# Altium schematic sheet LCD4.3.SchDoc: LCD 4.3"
size A4; Date: Not used; ApprovedBy: Not used; CheckedBy: Not used; Author: Not used; CompanyName: STMicroelectronics; DrawnBy: Not used; Engineer: Not used; Organization: Not used; Address1: Not used; Address2: Not used; Address3: Not used; Address4: Not used; DocumentNumber: 10; Revision: Not used; SheetNumber: 10; SheetTotal: 17
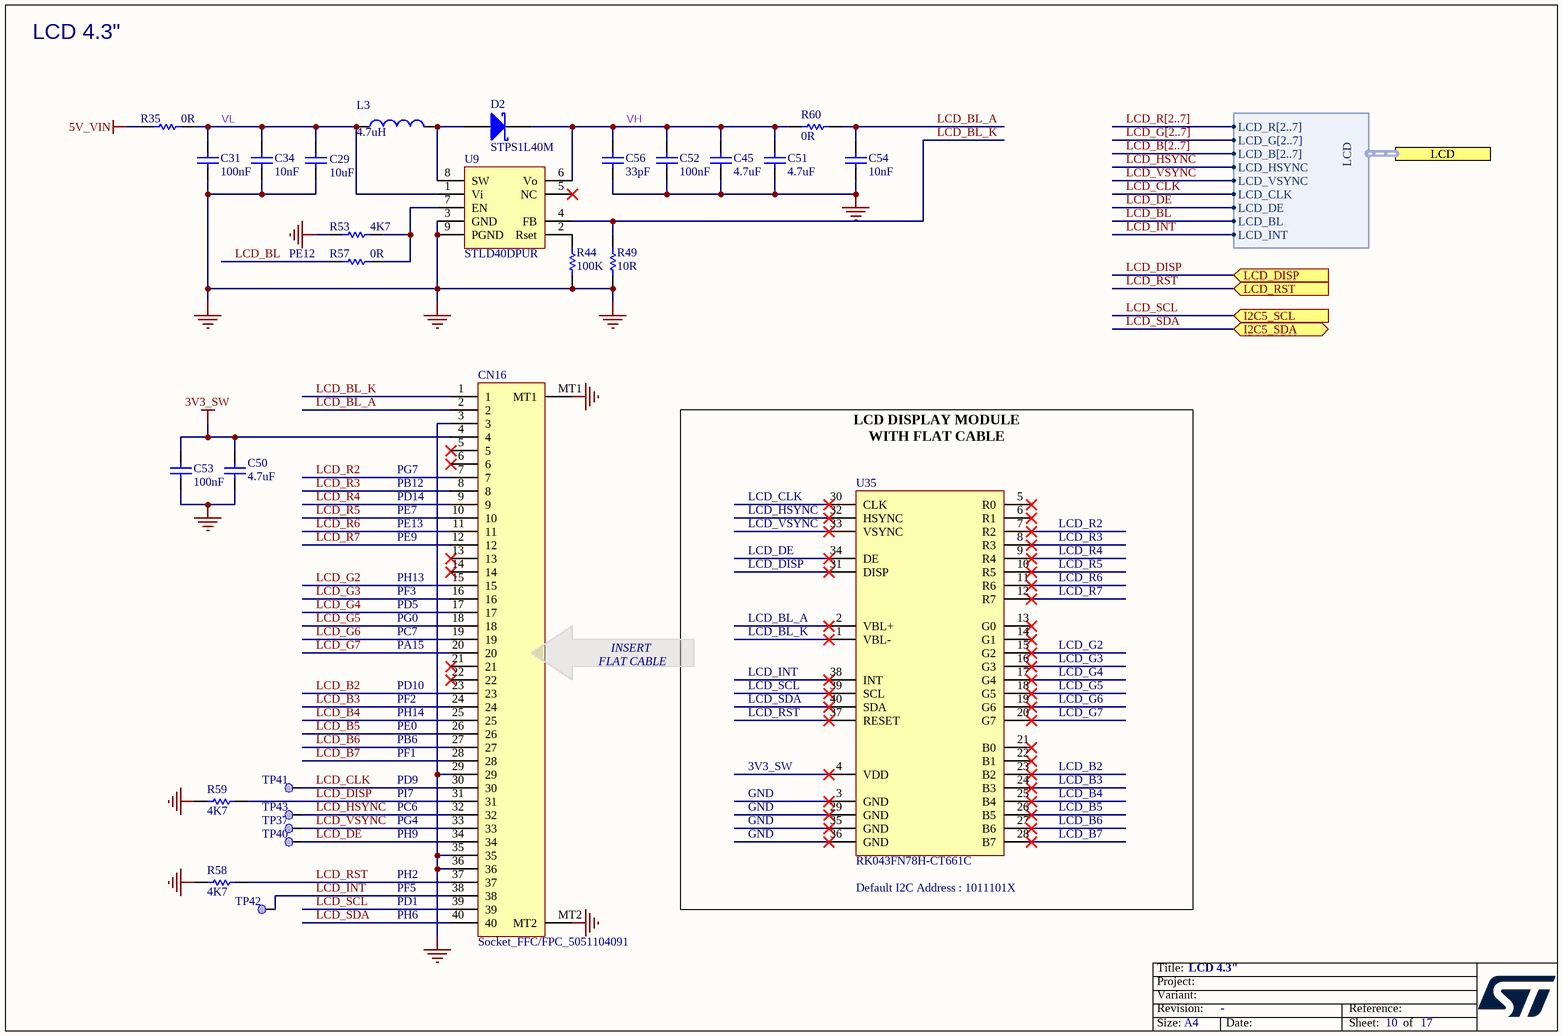
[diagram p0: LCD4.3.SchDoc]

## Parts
C29  value 10uF  [C0603]  (hidden comment: Capacitor)
C31  value 100nF  [C0402]  (hidden comment: Capacitor)
C34  value 10nF  [C0402]  (hidden comment: Capacitor)
C45  value 4.7uF  [C1206_H1P25]  (hidden comment: Capacitor)
C50  value 4.7uF  [C0402]  (hidden comment: Capacitor)
C51  value 4.7uF  [C1206_H1P25]  (hidden comment: Capacitor)
C52  value 100nF  [C0603]  (hidden comment: Capacitor)
C53  value 100nF  [C0402]  (hidden comment: Capacitor)
C54  value 10nF  [C0402]  (hidden comment: Capacitor)
C56  value 33pF  [C0402]  (hidden comment: Capacitor)
CN16  value Socket_FFC/FPC_5051104091  [CON_MOLEX_5051104091]  (hidden comment: 5051104091)
D2  STPS1L40M  [DIO_DO216-AA]
L3  value 4.7uH  [L1210_LQH]  (hidden comment: Inductor)
R35  value 0R  [R0603]  (hidden comment: Resistor)
R44  value 100K  [R0402]  (hidden comment: Resistor)
R49  value 10R  [R0603]  (hidden comment: Resistor)
R53  value 4K7  [R0402]  (hidden comment: Resistor)
R57  value 0R  [R0402]  (hidden comment: Resistor)
R58  value 4K7  [R0402]  (hidden comment: Resistor)
R59  value 4K7  [R0402]  (hidden comment: Resistor)
R60  value 0R  [R0402]  (hidden comment: Resistor)
TP37  Test Point  [TP_SMD_1MM]  (value not drawn)  (no BOM)
TP40  Test Point  [TP_SMD_1MM]  (value not drawn)  (no BOM)
TP41  Test Point  [TP_SMD_1MM]  (value not drawn)  (no BOM)
TP42  Test Point  [TP_SMD_1MM]  (value not drawn)  (no BOM)
TP43  Test Point  [TP_SMD_1MM]  (value not drawn)  (no BOM)
U9  STLD40DPUR  [ICC_QFN8-EPAD_3X3_P065]
U35  RK043FN78H-CT661C  [LCD_DRAWING_ROCKTEK_RK043FN78H-CT661C]

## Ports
I2C5_SCL (in), I2C5_SDA (bidir), LCD (harness LCD), LCD_DISP (in), LCD_RST (in)

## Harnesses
LCD: LCD_R[2..7], LCD_G[2..7], LCD_B[2..7], LCD_HSYNC, LCD_VSYNC, LCD_DE, LCD_CLK, LCD_BL, LCD_INT

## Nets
3V3_SW: C50.1 C53.2 CN16.4
5V_VIN: R35.1
GND: C29.2 C31.1 C34.1 C45.1 C50.2 C51.1 C52.1 C53.1 C54.1 C56.1 CN16.3 CN16.29 CN16.35 CN16.36 CN16.MT1 CN16.MT2 R44.1 R49.1 R53.1 R58.2 R59.1 U9.3(GND) U9.9(PGND)
LCD_B2: CN16.23
LCD_B3: CN16.24
LCD_B4: CN16.25
LCD_B5: CN16.26
LCD_B6: CN16.27
LCD_B7: CN16.28
LCD_BL: R57.1 ; port LCD.LCD_BL
LCD_BL_A: C54.2 CN16.2 R60.2
LCD_BL_K: CN16.1 R49.2 U9.4(FB)
LCD_CLK: CN16.30 TP41.1 ; port LCD.LCD_CLK
LCD_DE: CN16.34 TP40.1 ; port LCD.LCD_DE
LCD_DISP: CN16.31 R59.2 ; port LCD_DISP
LCD_G2: CN16.15
LCD_G3: CN16.16
LCD_G4: CN16.17
LCD_G5: CN16.18
LCD_G6: CN16.19
LCD_G7: CN16.20
LCD_HSYNC: CN16.32 TP43.1 ; port LCD.LCD_HSYNC
LCD_INT: CN16.38 TP42.1 ; port LCD.LCD_INT
LCD_R2: CN16.7
LCD_R3: CN16.8
LCD_R4: CN16.9
LCD_R5: CN16.10
LCD_R6: CN16.11
LCD_R7: CN16.12
LCD_RST: CN16.37 R58.1 ; port LCD_RST
LCD_SCL: CN16.39 ; port I2C5_SCL
LCD_SDA: CN16.40 ; port I2C5_SDA
LCD_VSYNC: CN16.33 TP37.1 ; port LCD.LCD_VSYNC
VH: C45.2 C51.2 C52.2 C56.2 D2.2(K) R60.1 U9.6(Vo)
VL: C29.1 C31.2 C34.2 L3.1 R35.2 U9.1(Vi)
NetD2_1: D2.1(A) L3.2 U9.8(SW)
NetR44_2: R44.2 U9.2(Rset)
NetR53_2: R53.2 R57.2 U9.7(EN)

Not connected (* = marked no-connect by the designer): CN16 5* 6* 13* 14* 21* 22*; U9 5(NC)*; U35 1(VBL-)* 2(VBL+)* 3(GND)* 4(VDD)* 5(R0)* 6(R1)* 7(R2)* 8(R3)* 9(R4)* 10(R5)* 11(R6)* 12(R7)* 13(G0)* 14(G1)* 15(G2)* 16(G3)* 17(G4)* 18(G5)* 19(G6)* 20(G7)* 21(B0)* 22(B1)* 23(B2)* 24(B3)* 25(B4)* 26(B5)* 27(B6)* 28(B7)* 29(GND)* 30(CLK)* 31(DISP)* 32(HSYNC)* 33(VSYNC)* 34(DE)* 35(GND)* 36(GND)* 37(RESET)* 38(INT)* 39(SCL)* 40(SDA)*

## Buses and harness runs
bus LCD_B[2..7]
bus LCD_G[2..7]
bus LCD_R[2..7]

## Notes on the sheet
- LCD 4.3"
- PE12
- PG7
- PB12
- PD14
- PE7
- LCD_CLK
- (near U35) LCD_HSYNC
- PE13
- PE9
- PH13
- (near U35) LCD_VSYNC
- LCD_DE
- LCD_DISP
- LCD_R2
- LCD_R3
- LCD_R4
- LCD_R5
- LCD_R6
- PF3
- PD5
- PG0
- PC7
- PA15
- (near CN16) INSERT
  FLAT CABLE
- LCD_BL_A
- LCD_BL_K
- LCD_R7
- LCD_G2
- PD10
- PF2
- PH14
- LCD_INT
- LCD_RST
- LCD_SCL
- LCD_SDA
- LCD_G3
- LCD_G4
- LCD_G5
- LCD_G6
- LCD_G7
- PE0
- PB6
- PF1
- PD9
- 3V3_SW
- LCD_B2
- LCD_B3
- PG4
- PC6
- PH9
- PI7
- GND
- LCD_B4
- LCD_B5
- LCD_B6
- LCD_B7
- PH6
- PD1
- PF5
- PH2
- (near U35) LCD DISPLAY MODULE
  WITH FLAT CABLE
- (near U35) Default I2C Address : 1011101X

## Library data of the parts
C29 = MCD-00099: Capacitor, MLCC, 10uF, 10V, X5R, +/-10%, 0603, T=0.8mm; Manufacturer_Part_Number: GRM188R61A106KE69; Manufacturer: MURATA; Part_Preference: Recommended; Partial_Alternate_Internal_Part_Number: MCD-03152; Order_Code_RS: 2494233; Component_Country_Of_Origin: Japan°°; ShowFields: YES; ID: 2770
C31 C53 = MCD-00006: Capacitor, MLCC, 100nF, 16V, X7R, +/-10%, 0402, T=0.5mm; Manufacturer_Part_Number: CC0402KRX7R7BB104; Manufacturer: YAGEO; Part_Preference: Recommended; Partial_Alternate_Internal_Part_Number: MCD-03299; Order_Code_RS: 9402047; Component_Country_Of_Origin: China; ShowFields: YES; ID: 2474
C34 C54 = MCD-02198: Capacitor, MLCC, 10nF, 50V, X7R, +/-10%, 0402, T=0.5mm; Manufacturer_Part_Number: CC0402KRX7R9BB103; Manufacturer: YAGEO; Part_Preference: Recommended; Order_Code_RS: 6169644; Component_Country_Of_Origin: China; ShowFields: YES; ID: 4298
C45 C51 = MCD-00013: Capacitor, MLCC, 4.7uF, 50V, X7R, +/-10%, 1206, T=1.27mm; Manufacturer_Part_Number: 12065C475KAT2A; Manufacturer: AVX; Part_Preference: Recommended; Partial_Alternate_Internal_Part_Number: MCD-03147; Order_Code_RS: 1908177; Component_Country_Of_Origin: China, Malaysia; ShowFields: YES; ID: 2466
C50 = MCD-01356: Capacitor, MLCC, 4.7uF, 6V3, X5R, +/-20%, 0402, T=0.5mm; Manufacturer_Part_Number: GRM155R60J475ME47; Manufacturer: MURATA; Part_Preference: Recommended; Partial_Alternate_Internal_Part_Number: MCD-04455; Order_Code_RS: 814-5230; Component_Country_Of_Origin: Japan°°; ShowFields: YES; ID: 3456
C52 = MCD-01099: Capacitor, MLCC, 100nF, 50V, X7R, +/-10%, 0603, T=0.8mm; BMS_Part_Number: 9142278; Part_Preference: Recommended; Manufacturer: YAGEO; Manufacturer_Part_Number: CC0603KRX7R9BB104; Order_Code_RS: 669-8767; Component_Country_Of_Origin: China; ShowFields: YES; ID: 3397
C56 = MCD-00277: Capacitor, MLCC, 33pF, 50V, NPO,+/-5%, 0402, T=0.5mm; Part_Preference: Recommended; Manufacturer: YAGEO; Manufacturer_Part_Number: CC0402JRNPO9BN330; Component_Country_Of_Origin: China; ShowFields: YES; ID: 2592
CN16 = MCD-02589: Socket_FFC/FPC, 40pins, 0.5mm, RA, SMD, T=1.9mm; Part_Type: Connector; Part_Preference: Recommended; Manufacturer: MOLEX; Order_Code_RS: 178-8776; ShowFields: YES; ID: 4695; Component_Country_Of_Origin: Japan
D2 = MCD-00033: Low Drop power Schottky rectifier(1A, 40V, 0.4V); Part_Type: Diode; Manufacturer: STMICROELECTRONICS; BMS_Part_Number: 9151085; Part_Preference: Recommended; Manufacturer_HQ_COO: EU; Component_Country_Of_Origin: China; ShowFields: YES; ID: 2485; Order_Code_RS: 189-4505
L3 = MCD-00048: Inductor, 4.7uH, +/-30%, 1A, 180mR, 1210, T=1.7mm; Manufacturer_Part_Number: LQH32PN4R7NN0L; Manufacturer: MURATA; Part_Preference: Recommended; Order_Code_RS: 2470296; Component_Country_Of_Origin: Japan°°; ShowFields: YES; ID: 2544
R35 = MCD-00181: Resistor, 0R, 0603, +/- 0.5mR, 1/4W; Part_Preference: Recommended; Manufacturer: ROHM SEMICONDUCTOR; Manufacturer_Part_Number: PMR03EZPJ000; Component_Country_Of_Origin: Philippines, Thailand°°; ShowFields: YES; ID: 2691
R44 = MCD-00059: Resistor, 100K, 0402, +/-1%, 1/16W; Manufacturer_Part_Number: RC0402FR-07100KL; Manufacturer: YAGEO; Part_Preference: Recommended; Partial_Alternate_Internal_Part_Number: MCD-03301; Order_Code_RS: 2421891; Component_Country_Of_Origin: China; ShowFields: YES; ID: 2533
R49 = MCD-00060: Resistor, 10R, 0603, +/-1%, 1/4W; Manufacturer_Part_Number: ESR03EZPF10R0; Manufacturer: ROHM SEMICONDUCTOR; Part_Preference: Recommended; Order_Code_RS: 2887146; Component_Country_Of_Origin: Philippines, Thailand°°; ShowFields: YES; ID: 2531
R53 R58 R59 = MCD-00065: Resistor, 4K7, 0402, +/-1%, 1/16W; Manufacturer_Part_Number: RC0402FR-074K7L; Manufacturer: YAGEO; Part_Preference: Recommended; Partial_Alternate_Internal_Part_Number: MCD-03300; Order_Code_RS: 9239316; Component_Country_Of_Origin: China; ShowFields: YES; ID: 2526
R57 = MCD-00052: Resistor, 0R, 0402, +/-5%, 1/16W; Manufacturer_Part_Number: RC0402JR-070RL; Manufacturer: YAGEO; Part_Preference: Recommended; Order_Code_RS: 9232516RL; Component_Country_Of_Origin: China; ShowFields: YES; ID: 2540
R60 = MCD-00052: Resistor, 0R, 0402, +/-5%, 1/16W; Part_Preference: Recommended; Manufacturer: YAGEO; Manufacturer_Part_Number: RC0402JR-070RL; Order_Code_RS: 9232516RL; Component_Country_Of_Origin: China; ShowFields: YES; ID: 2540
TP37 TP40-TP43 = MCD-00074: Test Point 1mm; Part_Type: Misc; Part_Preference: Recommended; ShowFields: YES; ID: 2518; Component_Country_Of_Origin: Unknown
U9 = MCD-00082: White LED power supply for large display backlight, QFN8; Part_Type: IC; Manufacturer: STMICROELECTRONICS; BMS_Part_Number: 9176009; Part_Preference: Recommended; Manufacturer_HQ_COO: EU; Component_Country_Of_Origin: Malaysia; ShowFields: YES; ID: 2510; Order_Code_RS: 188-9216
U35 = MCD-02422: LCD,  TFT, 4.3 inch, 480x272 pixels with LED Backlight and Capacitive touch panel, high luminance with 0.5mm pitch flat cable; Part_Type: Display; Manufacturer: ROCKTECH; Part_Preference: Not recommended; Component_Country_Of_Origin: Unknown; ShowFields: YES; ID: 4528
